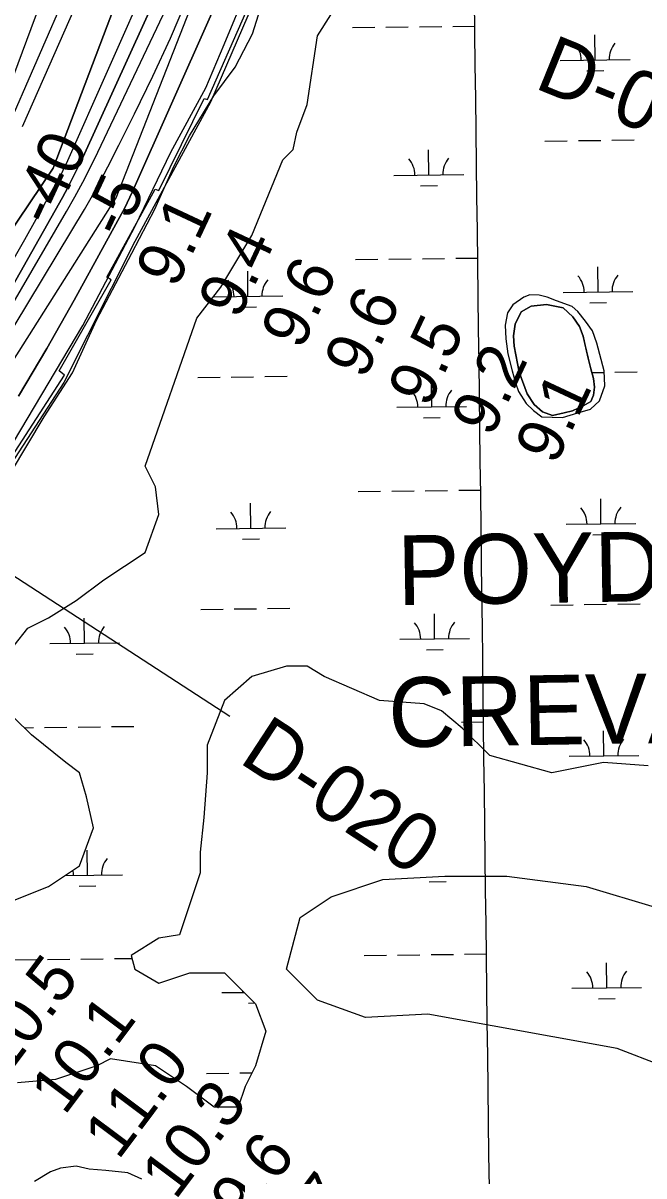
# Model space of a CAD drawing. Extents: x 3715084 to 3753216, y 488173 to 513963.
# Drawn here: x 3734453 to 3735343, y 500052 to 501705 of the extents above; entities that cross this region are included whole.
import ezdxf

# ---------------------------------------------------------------- set-up
doc = ezdxf.new("R2010")
doc.units = 0
for name, color, linetype in [('V-GRID-MAJR', 7, 'Continuous'), ('V-RIVR-CREV', 7, 'Continuous'), ('V-RIVR-EDGE', 7, 'Continuous'), ('V-RIVR-RANG', 7, 'Continuous'), ('V-RIVR-RANG-IDEN', 7, 'Continuous'), ('V-ROAD-CNTR', 7, 'Continuous'), ('V-RRAP-FSHR', 7, 'Continuous'), ('V-RRAP-RVMT', 7, 'Continuous'), ('V-SITE-VEGE', 7, 'Continuous'), ('V-TOPO-DPTH', 7, 'Continuous'), ('V-TOPO-MAJR', 7, 'Continuous'), ('V-TOPO-MINR', 7, 'Continuous'), ('V-TOPO-SHOR', 7, 'Continuous'), ('V-TOPO-WATR', 7, 'Continuous'), ('V-WETL-SWMP', 7, 'Continuous')]:
    doc.layers.add(name, color=color, linetype=linetype)

msp = doc.modelspace()

# ---------------------------------------------------------------- linework, layer by layer
at = {"layer": 'V-GRID-MAJR'}
msp.add_spline([(3735199.485, 493788.957), (3735123.717, 499845.93700000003), (3735047.9050000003, 505906.385), (3734972.094, 511966.84500000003), (3734972.051, 511970.3)], degree=3, dxfattribs=at)
at = {"layer": 'V-RIVR-EDGE'}
msp.add_lwpolyline([(3734410.1905545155, 501056.210652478), (3734538.5922544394, 501271.41041308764), (3734613.385595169, 501414.10320921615), (3734664.6757903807, 501520.2341972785), (3734714.7311978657, 501612.5607260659), (3734741.2983040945, 501674.32867640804), (3734807.1283643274, 501833.8527818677)], dxfattribs=at)
at = {"layer": 'V-RIVR-RANG'}
msp.add_line((3734749.435, 500710.7570000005), (3733843.8419, 501299.2306000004), dxfattribs=at)
at = {"layer": 'V-ROAD-CNTR'}
msp.add_spline([(3733715.5725298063, 498954.1440656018), (3733927.4081061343, 498985.4220030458), (3734149.04466286, 499017.4349390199), (3734317.1243267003, 499039.17989553), (3734452.533055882, 499051.021871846), (3734616.6037277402, 499062.12884963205), (3734803.4543540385, 499064.3688451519), (3734911.8351372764, 499064.8078442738), (3735132.1146967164, 499070.0368338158), (3735323.316314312, 499078.37181714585), (3735505.803949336, 499097.111779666), (3735898.0601648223, 499142.646688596), (3736237.231486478, 499184.4396050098), (3736547.3718661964, 499225.4965228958), (3736808.1873445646, 499257.56445876), (3736976.362008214, 499281.2394114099), (3737080.0268008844, 499296.4683809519), (3737176.0426088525, 499320.73933240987), (3737239.9724809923, 499343.32428724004), (3737319.351322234, 499377.88521811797), (3737388.8621832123, 499415.7931423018), (3737461.5770377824, 499455.86406216), (3737533.711893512, 499510.0739537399), (3737613.734733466, 499584.10580567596), (3737686.298588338, 499661.42465103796), (3737745.2314704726, 499744.2114854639), (3737793.210374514, 499828.8213162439), (3737831.048298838, 499907.621158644), (3737863.2922343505, 499993.6939864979), (3737884.48719196, 500070.0438337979), (3737902.013156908, 500150.4446729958), (3737918.8031233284, 500240.6464925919), (3737947.8120653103, 500405.0821637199), (3737975.5520098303, 500525.3699231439)], degree=3, dxfattribs=at)
at = {"layer": 'V-RRAP-FSHR'}
msp.add_lwpolyline([(3735311.1075297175, 503785.3337125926), (3735300.163017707, 503528.9671203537), (3735290.8016096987, 503381.7404962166), (3735268.0647136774, 503216.76590406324), (3735221.108169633, 502972.3452958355), (3735143.640521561, 502689.4980635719), (3735049.1048414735, 502444.89723134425), (3734990.0364254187, 502275.0258711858), (3734953.6844253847, 502144.4822550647), (3734836.9525212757, 501859.4047507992), (3734782.565833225, 501733.2745746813), (3734721.7914331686, 501591.9379985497), (3734612.9095130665, 501392.192462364), (3734511.3471449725, 501189.7824781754), (3734429.0626008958, 501063.2242700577), (3734270.7440087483, 500819.6617738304), (3734116.4825046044, 500553.80884558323), (3734047.9687125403, 500419.9310854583), (3733930.724808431, 500312.61383735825), (3733803.525576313, 500233.1985412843), (3733597.1629521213, 500150.03335720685), (3733341.941191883, 499958.17671702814)], dxfattribs=at)
at = {"layer": 'V-RRAP-RVMT'}
for p, q in [((3734717.0990000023, 501595.58400000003), (3734779.363000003, 501736.60100000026)), ((3734647.5110000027, 501465.06400000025), (3734712.705000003, 501597.07300000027)), ((3734712.705000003, 501597.07300000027), (3734717.0990000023, 501595.58400000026)), ((3734573.2270000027, 501341.14600000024), (3734642.1330000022, 501467.22300000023)), ((3734642.1330000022, 501467.22300000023), (3734647.5110000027, 501465.06400000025)), ((3734504.5470000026, 501206.69900000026), (3734579.0390000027, 501337.09100000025)), ((3734579.0390000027, 501337.09100000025), (3734573.2270000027, 501341.14600000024)), ((3734426.9820000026, 501068.168), (3734512.1710000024, 501200.33900000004)), ((3734512.171000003, 501200.33900000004), (3734504.5470000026, 501206.69900000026))]:
    msp.add_line(p, q, dxfattribs=at)
at = {"layer": 'V-SITE-VEGE'}
for points in [[(3734434.725, 501059.775), (3734483.136, 501140.604), (3734523.899, 501203.609), (3734558.302, 501279.35000000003), (3734608.627, 501375.454), (3734641.754, 501438.465), (3734669.148, 501499.565), (3734691.444, 501543.48), (3734726.477, 501600.761), (3734757.048, 501642.126), (3734781.892, 501689.86100000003), (3734801.649, 501754.15)], [(3734623.037, 500047.238), (3734603.145, 500056.67100000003), (3734571.7320000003, 500059.82300000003), (3734547.65, 500061.92600000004), (3734528.804, 500066.123), (3734506.815, 500062.989), (3734492.153, 500057.759), (3734469.111, 500044.156)]]:
    msp.add_lwpolyline(points, dxfattribs=at)
msp.add_lwpolyline([(3735217.731, 501307.213), (3735204.12, 501312.454), (3735192.602, 501315.075), (3735179.5130000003, 501315.603), (3735170.613, 501312.466), (3735154.9020000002, 501301.476), (3735147.569, 501289.96), (3735143.897, 501272.159), (3735144.937, 501252.267), (3735148.0700000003, 501230.802), (3735153.821, 501206.713), (3735159.0500000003, 501189.434), (3735163.234, 501176.868), (3735174.221, 501159.587), (3735184.6890000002, 501149.636), (3735196.727, 501140.731), (3735226.044, 501139.672), (3735248.037, 501146.469), (3735266.365, 501151.7), (3735279.458, 501163.73600000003), (3735286.796, 501185.199), (3735285.755, 501206.664), (3735275.298, 501246.45900000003), (3735269.023, 501263.74), (3735259.08, 501277.87700000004), (3735248.091, 501291.494), (3735240.239, 501298.826)], close=True, dxfattribs=at)
at = {"layer": 'V-TOPO-DPTH'}
for points in [[(3734808.0301714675, 502320.34369700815), (3734495.9, 501496.99), (3734209.516987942, 501071.8828028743)], [(3734808.0301714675, 502320.34369700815), (3734495.9, 501496.99), (3734209.516987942, 501071.8828028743)], [(3734802.391030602, 502092.3865371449), (3734538.4812860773, 501512.7191841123), (3734531.612114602, 501498.14618753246), (3734524.489675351, 501483.7022757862), (3734516.987334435, 501469.45199129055), (3734509.231725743, 501455.3307916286), (3734414.633088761, 501288.3669135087)], [(3734802.391030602, 502092.3865371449), (3734538.4812860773, 501512.7191841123), (3734531.612114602, 501498.14618753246), (3734524.489675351, 501483.7022757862), (3734516.987334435, 501469.45199129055), (3734509.231725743, 501455.3307916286), (3734414.633088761, 501288.3669135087)], [(3734889.549397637, 502092.66876364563), (3734609.8164074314, 501463.6273038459), (3734606.1644723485, 501455.48440955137), (3734602.36165038, 501447.4152463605), (3734598.332498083, 501439.45667982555), (3734594.1524589, 501431.57184439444), (3734526.2539382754, 501307.7526358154), (3734487.0011816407, 501238.6345959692), (3734446.4044106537, 501170.3428566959)], [(3734427.9853489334, 501347.1253487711), (3734455.3986129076, 501394.79971047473), (3734501.986042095, 501478.16284818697), (3734505.4426046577, 501484.5523435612), (3734508.7803755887, 501491.00127001), (3734511.9399590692, 501497.539343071), (3734514.980750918, 501504.1368472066), (3734636.659084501, 501777.96190838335)], [(3734427.9853489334, 501347.1253487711), (3734455.3986129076, 501394.79971047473), (3734501.986042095, 501478.16284818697), (3734505.4426046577, 501484.5523435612), (3734508.7803755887, 501491.00127001), (3734511.9399590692, 501497.539343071), (3734514.980750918, 501504.1368472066), (3734636.659084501, 501777.96190838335)], [(3734272.7741521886, 500993.96928800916), (3734523.063102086, 501407.7455063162), (3734540.7618813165, 501437.83076869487), (3734557.961734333, 501468.1906758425), (3734574.4131980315, 501498.96255014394), (3734590.3657355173, 501530.00906921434), (3734612.858638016, 501575.13513797), (3734638.939895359, 501629.28044375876), (3734664.032134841, 501683.8643186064), (3734687.6408475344, 501739.10604704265)], [(3734272.7741521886, 500993.96928800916), (3734523.063102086, 501407.7455063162), (3734540.7618813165, 501437.83076869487), (3734557.961734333, 501468.1906758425), (3734574.4131980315, 501498.96255014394), (3734590.3657355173, 501530.00906921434), (3734612.858638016, 501575.13513797), (3734638.939895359, 501629.28044375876), (3734664.032134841, 501683.8643186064), (3734687.6408475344, 501739.10604704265)]]:
    msp.add_lwpolyline(points, dxfattribs=at)
at = {"layer": 'V-TOPO-MAJR'}
msp.add_lwpolyline([(3734452.2072716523, 501556.87061773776), (3734749.047892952, 502229.7762877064)], dxfattribs=at)
at = {"layer": 'V-TOPO-MINR'}
for points in [[(3734405.25, 501539.21), (3734708.7804274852, 502355.04045915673)], [(3734209.516987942, 501071.8828028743), (3734495.9, 501496.99), (3734808.0301714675, 502320.34369700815)], [(3733355.6028054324, 500047.33560748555), (3733365.149511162, 500054.6299801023), (3733374.7260449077, 500061.88514816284), (3733384.322463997, 500069.1141798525), (3733520.1314309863, 500170.9840233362), (3733596.687825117, 500230.2789719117), (3733671.9678104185, 500291.10466721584), (3733745.333182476, 500354.2264826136), (3733817.422145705, 500418.87904473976), (3733998.289587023, 500586.20262373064), (3734021.474937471, 500608.7165113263), (3734043.8950347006, 500631.9344284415), (3734065.1672521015, 500656.2083898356), (3734085.674216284, 500681.1863807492), (3734094.6488101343, 500692.6732228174), (3734118.5857315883, 500724.2639940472), (3734141.883563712, 500756.3051526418), (3734164.22276184, 500789.021892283), (3734185.9228706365, 500822.1890192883), (3734586.5500000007, 501454.77), (3734909.6970344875, 502280.42160018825)], [(3734414.633088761, 501288.3669135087), (3734509.231725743, 501455.3307916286), (3734516.987334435, 501469.45199129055), (3734524.489675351, 501483.7022757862), (3734531.612114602, 501498.14618753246), (3734538.4812860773, 501512.7191841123), (3734802.391030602, 502092.3865371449)], [(3734427.9853489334, 501347.1253487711), (3734455.3986129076, 501394.79971047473), (3734501.986042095, 501478.16284818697), (3734505.4426046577, 501484.5523435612), (3734508.7803755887, 501491.00127001), (3734511.9399590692, 501497.539343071), (3734514.980750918, 501504.1368472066), (3734636.659084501, 501777.96190838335)], [(3734427.6457558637, 501547.6928389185), (3734518.66177486, 501756.6560893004)], [(3734272.7741521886, 500993.96928800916), (3734523.063102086, 501407.7455063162), (3734540.7618813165, 501437.83076869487), (3734557.961734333, 501468.1906758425), (3734574.4131980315, 501498.96255014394), (3734590.3657355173, 501530.00906921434), (3734612.858638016, 501575.13513797), (3734638.939895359, 501629.28044375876), (3734664.032134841, 501683.8643186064), (3734687.6408475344, 501739.10604704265)], [(3734355.144617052, 501160.56056119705), (3734515.290008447, 501435.0519764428), (3734527.152815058, 501455.99737140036), (3734538.6519131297, 501477.13463125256), (3734549.605448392, 501498.5596884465), (3734560.1952751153, 501520.1766105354), (3734658.419182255, 501727.36193362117)]]:
    msp.add_lwpolyline(points, dxfattribs=at)
at = {"layer": 'V-TOPO-SHOR'}
msp.add_lwpolyline([(3735211.99, 501142.50800000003), (3735197.454, 501147.571), (3735185.448, 501158.321), (3735175.339, 501173.49700000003), (3735163.973, 501204.47500000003), (3735157.032, 501241.773), (3735155.775, 501256.943), (3735158.308, 501273.378), (3735167.166, 501291.075), (3735181.074, 501299.287), (3735203.2, 501301.806), (3735227.217, 501296.74100000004), (3735241.119, 501284.093), (3735250.597, 501270.183), (3735255.65, 501256.275), (3735258.804, 501243), (3735263.223, 501224.666), (3735267.0100000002, 501209.494), (3735270.7970000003, 501195.587), (3735272.056, 501182.94200000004), (3735270.789, 501171.566), (3735266.994, 501162.716), (3735256.876, 501157.033), (3735240.4390000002, 501149.451), (3735228.4280000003, 501146.295), (3735211.99, 501142.50800000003)], dxfattribs=at)
at = {"layer": 'V-TOPO-WATR'}
msp.add_lwpolyline([(3734446.4044106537, 501170.3428566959), (3734487.0011816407, 501238.6345959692), (3734526.2539382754, 501307.7526358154), (3734594.1524589, 501431.57184439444), (3734598.332498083, 501439.45667982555), (3734602.36165038, 501447.4152463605), (3734606.1644723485, 501455.48440955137), (3734609.8164074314, 501463.6273038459), (3734889.549397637, 502092.66876364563)], dxfattribs=at)
at = {"layer": 'V-WETL-SWMP'}
for p, q in [((3734925.1349174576, 501698.8050881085), (3734957.1324188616, 501699.20496797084)), ((3734973.131169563, 501699.4049079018), (3735005.128670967, 501699.8047877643)), ((3735021.127421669, 501700.0047276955), (3735053.1249230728, 501700.4046075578)), ((3735069.1236737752, 501700.6045474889), (3735101.1211751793, 501701.00442735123)), ((3735273.0578831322, 501652.40719617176), (3735272.608018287, 501688.40438525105)), ((3735223.0617871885, 501651.7823838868), (3735323.053979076, 501653.0320084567)), ((3735261.2516496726, 501636.8274460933), (3735285.2497757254, 501637.1273559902)), ((3735201.098081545, 501536.0668848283), (3735233.0955829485, 501536.46676469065)), ((3735249.0943336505, 501536.66670462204), (3735281.0918350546, 501537.0665844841)), ((3735297.0905857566, 501537.2665244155), (3735329.08808716, 501537.66640427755)), ((3735034.6273267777, 501487.5528373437), (3735034.1774619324, 501523.5500264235)), ((3734984.631230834, 501486.92802505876), (3735084.6234227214, 501488.17764962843)), ((3735022.8210933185, 501471.9730872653), (3735046.8192193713, 501472.27299716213)), ((3734929.2921059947, 501366.1560637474), (3734961.289607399, 501366.55594360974)), ((3734977.288358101, 501366.75588354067), (3735009.2858595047, 501367.15576340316)), ((3735025.2846102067, 501367.3557033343), (3735057.2821116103, 501367.75558319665)), ((3735073.2808623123, 501367.9555231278), (3735105.2783637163, 501368.3554029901)), ((3734775.3462612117, 501313.486206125), (3734774.8963963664, 501349.4833952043)), ((3735277.21507167, 501319.75817181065), (3735276.7652068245, 501355.75536088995)), ((3735227.2189757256, 501319.1333595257), (3735327.211167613, 501320.3829840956)), ((3734725.8737800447, 501312.86793756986), (3734825.3423571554, 501314.11101840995)), ((3735265.40883821, 501304.1784217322), (3735289.406964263, 501304.47833162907)), ((3734763.540027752, 501297.90645604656), (3734787.538153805, 501298.2063659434)), ((3735268.4494270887, 501204.2076118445), (3735285.249023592, 501204.41756012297)), ((3735301.247774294, 501204.61750005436), (3735333.2452756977, 501205.01737991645)), ((3734703.3864596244, 501197.1458947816), (3734735.383961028, 501197.5457746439)), ((3734751.38271173, 501197.7457145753), (3734783.380213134, 501198.1455944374)), ((3734799.378963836, 501198.34553436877), (3734831.37646524, 501198.74541423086)), ((3735038.784515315, 501154.90381298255), (3735038.33465047, 501190.9010020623)), ((3734988.7884193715, 501154.2790006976), (3735088.780611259, 501155.52862526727)), ((3735026.978281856, 501139.3240629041), (3735050.976407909, 501139.62397280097)), ((3734981.4455466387, 501034.1068591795), (3735013.4430480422, 501034.50673904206)), ((3735029.4417987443, 501034.7066789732), (3735061.4393001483, 501035.10655883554)), ((3735077.43805085, 501035.30649876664), (3735109.435552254, 501035.70637862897)), ((3734933.449294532, 501033.50703938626), (3734965.4467959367, 501033.9069192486)), ((3735281.3722602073, 500987.1091474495), (3735280.922395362, 501023.1063365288)), ((3734779.503449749, 500980.8371817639), (3734779.053584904, 501016.8343708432)), ((3735231.376164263, 500986.48433516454), (3735331.3683561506, 500987.73395973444)), ((3734729.5073538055, 500980.21236947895), (3734829.499545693, 500981.46199404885)), ((3735269.5660267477, 500971.52939737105), (3735293.5641528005, 500971.8293072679)), ((3734767.6972162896, 500965.25743168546), (3734791.6953423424, 500965.5573415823)), ((3735209.41245862, 500870.7688361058), (3735241.409960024, 500871.16871596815)), ((3735257.408710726, 500871.36865589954), (3735289.4062121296, 500871.7685357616)), ((3735305.4049628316, 500871.968475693), (3735337.402464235, 500872.36835555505)), ((3734707.543648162, 500864.49687042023), (3734739.541149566, 500864.89675028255)), ((3734755.5399002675, 500865.09669021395), (3734787.5374016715, 500865.496570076)), ((3734803.5361523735, 500865.6965100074), (3734835.5336537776, 500866.09638986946)), ((3735042.9417038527, 500822.2547886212), (3735042.4918390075, 500858.251977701)), ((3734541.072893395, 500815.98282293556), (3734540.62302855, 500851.9800120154)), ((3734992.9456079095, 500821.62997633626), (3735092.9377997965, 500822.87960090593)), ((3734491.0767974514, 500815.35801065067), (3734591.068989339, 500816.6076352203)), ((3735031.1354703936, 500806.6750385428), (3735055.1335964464, 500806.97494843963)), ((3734529.266659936, 500800.4030728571), (3734553.2647859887, 500800.702982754)), ((3734454.437257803, 500694.8197421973), (3734467.735174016, 500694.9859292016)), ((3734483.733924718, 500695.1858691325), (3734515.7314261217, 500695.5857489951)), ((3734531.7301768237, 500695.78568892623), (3734563.7276782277, 500696.18556878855)), ((3734579.7264289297, 500696.3855087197), (3734611.7239303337, 500696.785388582)), ((3735081.5952393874, 500702.6574744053), (3735113.5927407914, 500703.0573542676)), ((3735285.529448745, 500654.46012308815), (3735285.0795838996, 500690.4573121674)), ((3735235.533352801, 500653.8353108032), (3735335.525544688, 500655.0849353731)), ((3734545.230081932, 500483.33379857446), (3734544.780217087, 500519.3309876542)), ((3734513.37277403, 500482.9356707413), (3734595.226177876, 500483.9586108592)), ((3735035.2926589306, 500474.0260141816), (3735059.290784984, 500474.32592407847)), ((3734533.423848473, 500467.754048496), (3734557.421974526, 500468.0539583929)), ((3734439.8948611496, 500361.93702497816), (3734471.8923625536, 500362.3369048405)), ((3734487.8911132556, 500362.5368447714), (3734519.888614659, 500362.93672463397)), ((3734535.887365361, 500363.13666456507), (3734567.8848667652, 500363.5365444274)), ((3734583.883617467, 500363.73648435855), (3734609.157219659, 500364.0523341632)), ((3734941.7636716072, 500368.20899066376), (3734973.7611730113, 500368.6088705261)), ((3734989.7599237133, 500368.808810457), (3735021.7574251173, 500369.20869031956)), ((3735037.7561758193, 500369.4086302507), (3735069.7536772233, 500369.808510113)), ((3735085.7524279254, 500370.00845004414), (3735117.749929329, 500370.40832990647)), ((3735289.686637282, 500321.811098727), (3735289.236772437, 500357.8082878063)), ((3734737.8217308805, 500314.91432075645), (3734769.726325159, 500315.3130395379)), ((3735239.690541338, 500321.18628644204), (3735339.682733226, 500322.43591101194)), ((3734776.0115933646, 500299.95938296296), (3734784.967712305, 500300.0713095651)), ((3735277.8804038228, 500306.23134864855), (3735301.878529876, 500306.5312585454)), ((3734715.858025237, 500199.19882169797), (3734747.855526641, 500199.5987015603)), ((3734763.854277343, 500199.7986414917), (3734780.854548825, 500200.0110976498))]:
    msp.add_line(p, q, dxfattribs=at)
for points in [[(3734440.1520000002, 500812.842), (3734459.911, 500837.541), (3734489.5500000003, 500852.36100000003), (3734529.069, 500877.06), (3734568.588, 500906.699), (3734627.866, 500946.217), (3734647.625, 501000.555), (3734642.685, 501040.074), (3734627.866, 501069.713), (3734701.963, 501282.126), (3734736.542, 501326.58400000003), (3734781, 501400.68200000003), (3734825.4590000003, 501509.358), (3734840.278, 501524.178), (3734845.218, 501548.87700000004), (3734860.038, 501588.395), (3734874.8570000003, 501687.19200000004), (3735062.571, 501983.582)], [(3735349.0810000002, 500639.94800000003), (3735284.863, 500644.88800000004), (3735210.7660000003, 500630.068), (3735121.849, 500654.767), (3735082.33, 500694.286), (3735052.691, 500718.985), (3735027.992, 500728.865), (3734963.774, 500733.805), (3734884.737, 500768.38300000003), (3734860.038, 500783.20300000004), (3734830.399, 500783.20300000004), (3734781, 500768.38300000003), (3734741.4820000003, 500733.805), (3734716.7830000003, 500669.587), (3734716.7830000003, 500630.068), (3734711.843, 500565.85000000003), (3734706.903, 500516.452), (3734706.903, 500486.813), (3734677.264, 500397.896), (3734647.625, 500392.956), (3734608.106, 500368.257), (3734613.046, 500348.498), (3734647.625, 500328.738), (3734692.0840000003, 500343.558), (3734741.4820000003, 500343.558), (3734785.94, 500299.099), (3734800.7600000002, 500259.581), (3734785.94, 500210.18200000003), (3734771.1210000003, 500180.544), (3734761.241, 500150.905), (3734726.662, 500150.905), (3734687.144, 500180.544), (3734642.685, 500210.18200000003), (3734578.467, 500220.06200000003), (3734558.708, 500210.18200000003), (3734499.43, 500190.423), (3734445.092, 500185.483)], [(3734440.1520000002, 500447.294), (3734489.5500000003, 500467.054), (3734534.009, 500496.693), (3734553.768, 500551.031), (3734543.889, 500595.489), (3734534.009, 500630.068), (3734514.25, 500644.88800000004), (3734464.8510000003, 500684.406), (3734440.1520000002, 500709.105)], [(3735368.84, 500210.18200000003), (3735304.623, 500234.882), (3735032.932, 500284.28), (3734944.015, 500279.34), (3734874.8570000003, 500304.039), (3734830.399, 500348.498), (3734850.1580000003, 500422.59500000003), (3734894.617, 500452.234), (3734968.714, 500476.933), (3735057.631, 500481.873), (3735146.548, 500481.873), (3735260.164, 500467.054), (3735358.961, 500437.41500000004)]]:
    msp.add_lwpolyline(points, dxfattribs=at)
msp.add_lwpolyline([(3735211.991, 501142.509), (3735228.427, 501146.29600000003), (3735240.4390000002, 501149.452), (3735256.877, 501157.032), (3735266.9930000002, 501162.717), (3735270.789, 501171.565), (3735272.057, 501182.943), (3735270.7970000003, 501195.586), (3735267.0100000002, 501209.494), (3735263.223, 501224.666), (3735255.649, 501256.275), (3735250.597, 501270.183), (3735241.12, 501284.093), (3735227.218, 501296.74100000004), (3735203.2, 501301.806), (3735181.074, 501299.286), (3735167.165, 501291.074), (3735158.309, 501273.378), (3735155.774, 501256.943), (3735157.0330000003, 501241.772), (3735163.973, 501204.47500000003), (3735175.339, 501173.49700000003), (3735185.448, 501158.322), (3735197.454, 501147.572)], close=True, dxfattribs=at)
for centre, radius, start, end in [((3735217.813327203, 501652.1916329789), 35.24628790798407, 359.94418071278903, 41.48783904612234), ((3735328.2905725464, 501653.5722915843), 35.246287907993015, 139.9441777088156, 181.48783604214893), ((3734979.3827708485, 501487.3372741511), 35.24628790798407, 359.94418071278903, 41.48783904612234), ((3735089.860016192, 501488.7179327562), 35.246287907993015, 139.9441777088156, 181.48783604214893), ((3734720.1017052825, 501313.2706429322), 35.24628790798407, 359.94418071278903, 41.48783904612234), ((3734830.578950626, 501314.6513015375), 35.246287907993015, 139.9441777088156, 181.48783604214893), ((3735221.9705157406, 501319.5426086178), 35.24628790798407, 359.94418071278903, 41.48783904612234), ((3735332.4477610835, 501320.9232672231), 35.246287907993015, 139.9441777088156, 181.48783604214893), ((3734983.539959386, 501154.68824978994), 35.24628790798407, 359.94418071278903, 41.48783904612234), ((3735094.01720473, 501156.0689083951), 35.246287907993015, 139.9441777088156, 181.48783604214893), ((3734724.25889382, 500980.62161857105), 35.24628790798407, 359.94418071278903, 41.48783904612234), ((3734834.7361391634, 500982.00227717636), 35.246287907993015, 139.9441777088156, 181.48783604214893), ((3735226.127704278, 500986.89358425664), 35.24628790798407, 359.94418071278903, 41.48783904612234), ((3735336.6049496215, 500988.274242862), 35.246287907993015, 139.9441777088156, 181.48783604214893), ((3734485.8283374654, 500815.767259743), 35.24628790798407, 359.94418071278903, 41.48783904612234), ((3734596.3055828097, 500817.1479183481), 35.246287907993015, 139.9441777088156, 181.48783604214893), ((3734987.6971479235, 500822.0392254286), 35.24628790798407, 359.94418071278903, 41.48783904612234), ((3735098.1743932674, 500823.4198840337), 35.246287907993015, 139.9441777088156, 181.48783604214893), ((3735230.2848928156, 500654.2445598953), 35.24628790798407, 359.94418071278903, 41.48783904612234), ((3735340.762138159, 500655.6252185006), 35.246287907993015, 139.9441777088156, 181.48783604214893), ((3734600.462771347, 500484.4988939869), 35.246287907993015, 139.9441777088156, 181.48783604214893), ((3734489.985526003, 500483.11823538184), 35.24628790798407, 359.94418071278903, 11.827820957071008), ((3735234.442081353, 500321.59553553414), 35.24628790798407, 359.94418071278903, 41.48783904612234), ((3735344.9193266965, 500322.9761941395), 35.246287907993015, 139.9441777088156, 181.48783604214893), ((3734732.573270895, 500315.32356984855), 35.24628790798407, 359.94418071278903, 3.17196078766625)]:
    msp.add_arc(centre, radius, start, end, dxfattribs=at)

# ---------------------------------------------------------------- texts
at = {"layer": 'V-RIVR-CREV'}
for s, p in [('POYDRAS', (3734990.0611619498, 500870.50473988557)), ('CREVASSE', (3734977.2211183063, 500666.62189296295))]:
    msp.add_text(s, height=100.00000199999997, rotation=0.9179915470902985, dxfattribs=at).set_placement(p)
at = {"layer": 'V-RIVR-RANG'}
for s, height, rotation, p in [('-40', 67.00000000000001, 65.16883333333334, (3734493.0749648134, 501411.1049470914)), ('-5', 66.99999999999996, 64.8883257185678, (3734595.2825067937, 501394.45753118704)), ('9.1', 66.99999999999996, 64.8883257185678, (3734672.2763641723, 501323.0991110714)), ('9.4', 66.99999999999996, 64.8883257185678, (3734761.9198700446, 501278.73048171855)), ('9.6', 66.99999999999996, 64.8883257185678, (3734851.787263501, 501234.8405477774)), ('9.6', 66.99999999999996, 64.8883257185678, (3734942.4382635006, 501192.62154777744)), ('9.5', 66.99999999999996, 64.8883257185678, (3735033.8718700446, 501152.07448171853)), ('9.2', 66.99999999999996, 64.8883257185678, (3735124.5228700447, 501109.85548171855)), ('9.1', 66.99999999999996, 64.8883257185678, (3735216.1813641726, 501069.78611107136)), ('10.5', 66.99999999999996, 53.17832571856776, (3734430.777384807, 500195.3600240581)), ('10.1', 66.99999999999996, 53.17832571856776, (3734512.4021952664, 500137.5304348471)), ('11.0', 66.99999999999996, 53.17832571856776, (3734589.4413942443, 500073.57729976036)), ('10.3', 66.99999999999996, 53.17832571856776, (3734671.382384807, 500016.17102405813)), ('9.6', 66.99999999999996, 53.17832571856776, (3734770.3971008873, 499981.5686778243)), ('9.7', 66.99999999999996, 53.17832571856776, (3734851.705731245, 499923.3167751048))]:
    msp.add_text(s, height=height, rotation=rotation, dxfattribs=at).set_placement(p)
at = {"layer": 'V-RIVR-RANG-IDEN'}
for s, rotation, p in [('D-010', 337.92532571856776, (3735183.911197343, 501612.89282174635)), ('D-020', 326.84132571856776, (3734760.475353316, 500646.090990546))]:
    msp.add_text(s, height=83, rotation=rotation, dxfattribs=at).set_placement(p)

doc.saveas('drawing.dxf')
